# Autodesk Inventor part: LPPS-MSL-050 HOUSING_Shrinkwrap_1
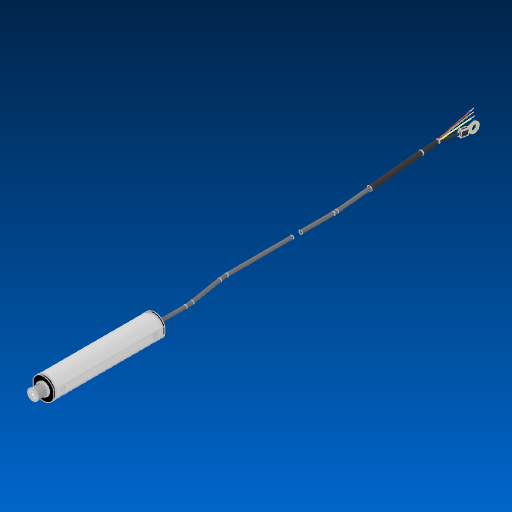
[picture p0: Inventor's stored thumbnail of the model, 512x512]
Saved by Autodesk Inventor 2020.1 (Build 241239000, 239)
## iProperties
Created: 2019-07
Part Number: LPPS-MSL-050 HOUSING_Shrinkwrap_1
Material: Generic
Document SubType Name: Modeling
Designer: J. Nielson
Density: 1 g/cm^3
Appearance: Default
Author: J. Nielson
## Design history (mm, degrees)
node "Assembly1"
body "Solid1"
node "Part1:1"
node "Part2:1"
body "Solid2"
node "Part3:1"
body "Solid3"
node "Part4:1"
body "Solid4"
node "Part5:1"
body "Solid5"
node "Part6:1"
body "Solid6"
node "Part7:1"
body "Solid7"
node "Part8:1"
body "Solid8"
node "Part9:1"
body "Solid9"
node "Part10:1"
body "Solid10"
node "Part11:1"
body "Solid11"
node "Part12:1"
body "Solid12"
node "Part13:1"
body "Solid13"
node "Part14:1"
body "Solid14"
node "Part15:1"
body "Solid15"
node "Part16:1"
body "Solid16"
node "Part17:1"
body "Solid17"
node "Part16:2"
body "Solid18"
node "Part17:2"
body "Solid19"
